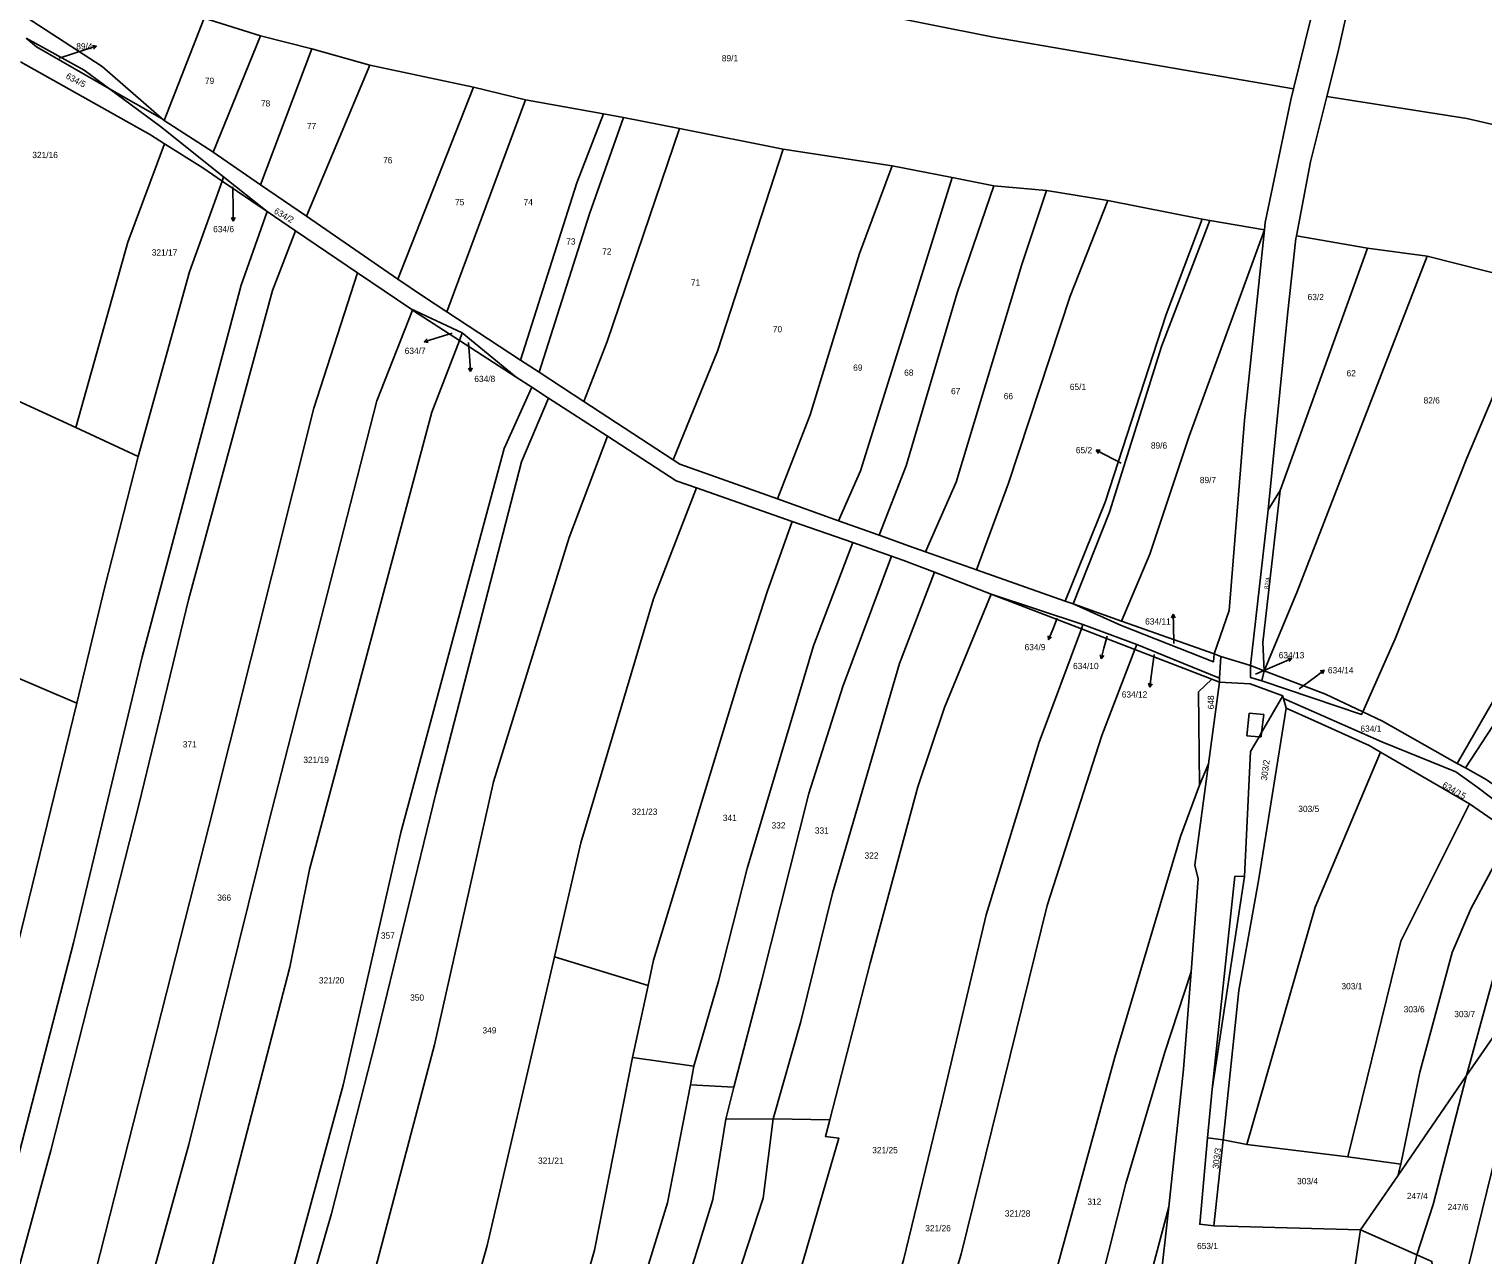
# Model space of a CAD drawing. Extents: x -744566 to -741843, y -1128407 to -1126744.
# Drawn here: x -743655.8 to -743260.5, y -1127679.3 to -1127345.9 of the extents above; entities that cross this region are included whole.
import ezdxf

# ---------------------------------------------------------------- set-up
doc = ezdxf.new("R2010")
doc.units = 0
for name, color, linetype in [('Hranice parcel', 7, 'Continuous'), ('Parcelní čísla', 7, 'Continuous'), ('Pop  PČ popisy', 7, 'Continuous'), ('Vnitřní kresba', 7, 'Continuous')]:
    doc.layers.add(name, color=color, linetype=linetype)

msp = doc.modelspace()

# ---------------------------------------------------------------- linework, layer by layer
at = {"layer": 'Hranice parcel'}
for p, q in [((-743312.01, -1127362.15), (-743304.91, -1127333.26)), ((-743608.18, -1127342.94), (-743619.02, -1127370.74)), ((-743608.18, -1127342.94), (-743592.88, -1127347.72)), ((-743592.88, -1127347.72), (-743605.72, -1127379.4)), ((-743592.88, -1127347.72), (-743578.94, -1127351.24)), ((-743578.94, -1127351.24), (-743592.83, -1127388.25)), ((-743578.94, -1127351.24), (-743563.19, -1127355.67)), ((-743563.19, -1127355.67), (-743580.36, -1127396.81)), ((-743563.19, -1127355.67), (-743534.99, -1127361.65)), ((-743534.99, -1127361.65), (-743555.5, -1127413.88)), ((-743534.99, -1127361.65), (-743520.78, -1127365.13)), ((-743520.78, -1127365.13), (-743542.21, -1127422.8)), ((-743520.78, -1127365.13), (-743499.65, -1127368.91)), ((-743499.65, -1127368.91), (-743494.17, -1127369.95)), ((-743494.17, -1127369.95), (-743478.91, -1127372.96)), ((-743478.91, -1127372.96), (-743450.74, -1127378.54)), ((-743592.83, -1127388.25), (-743605.72, -1127379.4)), ((-743450.74, -1127378.54), (-743421.13, -1127383.11)), ((-743603.32, -1127387.24), (-743602.9, -1127386.07)), ((-743602.9, -1127386.07), (-743591.07, -1127395.53)), ((-743421.13, -1127383.11), (-743404.84, -1127386.3)), ((-743591.07, -1127395.53), (-743603.32, -1127387.24)), ((-743580.36, -1127396.81), (-743592.83, -1127388.25)), ((-743404.84, -1127386.3), (-743393.46, -1127388.49)), ((-743393.46, -1127388.49), (-743379.14, -1127389.77)), ((-743379.14, -1127389.77), (-743362.5, -1127392.49)), ((-743362.5, -1127392.49), (-743336.87, -1127397.58)), ((-743591.07, -1127395.53), (-743583.33, -1127400.78)), ((-743555.5, -1127413.88), (-743580.36, -1127396.81)), ((-743336.87, -1127397.58), (-743334.8, -1127397.99)), ((-743583.33, -1127400.78), (-743566.53, -1127412.16)), ((-743334.8, -1127397.99), (-743319.91, -1127400.47)), ((-743291.86, -1127405.49), (-743315.66, -1127471.33)), ((-743291.86, -1127405.49), (-743311.22, -1127402.11)), ((-743275.71, -1127407.69), (-743291.86, -1127405.49)), ((-743244.94, -1127415.47), (-743275.71, -1127407.69)), ((-743566.53, -1127412.16), (-743552.04, -1127421.98)), ((-743551.54, -1127422.32), (-743552.04, -1127421.98)), ((-743552.04, -1127421.98), (-743538.08, -1127428.5)), ((-743538.8, -1127430.57), (-743551.54, -1127422.32)), ((-743522.16, -1127435.9), (-743542.21, -1127422.8)), ((-743538.8, -1127430.57), (-743538.08, -1127428.5)), ((-743538.08, -1127428.5), (-743523.36, -1127440.58)), ((-743695.91, -1127430.01), (-743643.11, -1127454.25)), ((-743523.36, -1127440.58), (-743538.8, -1127430.57)), ((-743517.11, -1127439.2), (-743522.16, -1127435.9)), ((-743523.36, -1127440.58), (-743519.14, -1127443.31)), ((-743504.93, -1127447.16), (-743517.11, -1127439.2)), ((-743519.14, -1127443.31), (-743514.57, -1127446.27)), ((-743514.57, -1127446.27), (-743498.56, -1127456.64)), ((-743480.64, -1127463.02), (-743504.93, -1127447.16)), ((-743643.11, -1127454.25), (-743626.1, -1127462.14)), ((-743474.35, -1127470.68), (-743448.36, -1127479.77)), ((-743318.91, -1127476.67), (-743315.66, -1127471.33)), ((-743435.76, -1127479.58), (-743452.29, -1127473.67)), ((-743318.91, -1127476.67), (-743323.69, -1127519.01)), ((-743448.36, -1127479.77), (-743431.85, -1127485.54)), ((-743424.7, -1127483.53), (-743435.76, -1127479.58)), ((-743431.85, -1127485.54), (-743421.29, -1127489.23)), ((-743398.17, -1127492.95), (-743412.06, -1127488.04)), ((-743409.64, -1127493.62), (-743394.17, -1127499.58)), ((-743374.07, -1127501.47), (-743398.17, -1127492.95)), ((-743369.67, -1127509.02), (-743394.17, -1127499.58)), ((-743394.17, -1127499.58), (-743369.28, -1127507.84)), ((-743371.91, -1127502.23), (-743374.07, -1127501.47)), ((-743371.91, -1127502.23), (-743358.75, -1127506.88)), ((-743369.67, -1127509.02), (-743369.28, -1127507.84)), ((-743369.28, -1127507.84), (-743354.63, -1127513.28)), ((-743358.75, -1127506.88), (-743333.57, -1127515.78)), ((-743355.14, -1127514.62), (-743369.67, -1127509.02)), ((-743355.14, -1127514.62), (-743354.63, -1127513.28)), ((-743334.26, -1127522.66), (-743355.14, -1127514.62)), ((-743354.63, -1127513.28), (-743332.1, -1127522.4)), ((-743331.74, -1127516.48), (-743333.57, -1127515.78)), ((-743331.74, -1127516.48), (-743332.1, -1127522.4)), ((-743323.69, -1127519.01), (-743331.74, -1127516.48)), ((-743323.69, -1127519.01), (-743320, -1127520.42)), ((-743320.65, -1127523.16), (-743320, -1127520.42)), ((-743642.79, -1127529.21), (-743661.46, -1127521.24)), ((-743335.16, -1127545.74), (-743332.17, -1127523.47)), ((-743332.17, -1127523.47), (-743334.26, -1127522.66)), ((-743332.1, -1127522.4), (-743332.17, -1127523.47)), ((-743314.71, -1127527.98), (-743314.91, -1127527.24)), ((-743314.01, -1127530.6), (-743314.71, -1127527.98)), ((-743265.25, -1127546.83), (-743254.82, -1127530.84)), ((-743264.18, -1127556.62), (-743288.35, -1127542.49)), ((-743337.56, -1127551.48), (-743335.16, -1127545.74)), ((-743265.25, -1127546.83), (-743267.48, -1127545.58)), ((-743252.73, -1127564.48), (-743264.18, -1127556.62)), ((-743230.52, -1127580.51), (-743264.95, -1127630.5)), ((-743487.51, -1127605.98), (-743512.98, -1127598.18)), ((-743491.75, -1127625.57), (-743487.51, -1127605.98)), ((-743475.06, -1127627.97), (-743491.75, -1127625.57)), ((-743475.06, -1127627.97), (-743475.93, -1127632.96)), ((-743264.95, -1127630.5), (-743283.69, -1127657.72)), ((-743475.93, -1127632.96), (-743464.14, -1127633.66)), ((-743464.14, -1127633.66), (-743466.39, -1127642.3)), ((-743453.46, -1127642.28), (-743466.39, -1127642.3)), ((-743453.46, -1127642.28), (-743438.1, -1127642.54)), ((-743335.37, -1127647.41), (-743331.17, -1127647.95)), ((-743333.67, -1127671.36), (-743331.17, -1127647.95)), ((-743324.73, -1127649.24), (-743331.17, -1127647.95)), ((-743324.73, -1127649.24), (-743297.22, -1127652.59)), ((-743282.86, -1127654.54), (-743297.22, -1127652.59)), ((-743283.69, -1127657.72), (-743282.86, -1127654.54)), ((-743283.69, -1127657.72), (-743293.8, -1127672.4)), ((-743333.67, -1127671.36), (-743293.8, -1127672.4)), ((-743301.55, -1127724.14), (-743293.8, -1127672.4)), ((-743293.8, -1127672.4), (-743278.45, -1127679.23)), ((-743287.1, -1127719.44), (-743278.45, -1127679.23))]:
    msp.add_line(p, q, dxfattribs=at)
for points in [[(-743312.01, -1127362.15), (-743393.56, -1127348.06), (-743446.91, -1127337.38), (-743506.37, -1127328.2), (-743565.99, -1127315.69), (-743593.43, -1127306.05), (-743622.26, -1127292.92), (-743649.24, -1127274.28)], [(-743677.33, -1127316.28), (-743670.54, -1127324.52), (-743664.92, -1127332.9), (-743656.54, -1127342.61), (-743635.91, -1127356.08), (-743619.02, -1127370.74)], [(-743296.23, -1127335.74), (-743299.98, -1127352.31), (-743302.98, -1127364.26)], [(-743656.57, -1127348.37), (-743640.77, -1127357.07), (-743633.94, -1127362.12)], [(-743656.57, -1127348.37), (-743653.73, -1127350.76), (-743633.94, -1127362.12)], [(-743618.94, -1127377.12), (-743622.79, -1127374.68), (-743658.11, -1127354.78)], [(-743633.94, -1127362.12), (-743620.04, -1127372.41), (-743602.9, -1127386.07)], [(-743619.02, -1127370.74), (-743619.65, -1127370.33), (-743633.94, -1127362.12)], [(-743319.91, -1127400.47), (-743319.7, -1127398.48), (-743312.73, -1127365.1), (-743312.01, -1127362.15)], [(-743302.98, -1127364.26), (-743307.41, -1127381.95), (-743311.22, -1127402.11)], [(-743199.65, -1127385.13), (-743264.92, -1127370.24), (-743302.98, -1127364.26)], [(-743499.65, -1127368.91), (-743506.82, -1127387.68), (-743522.16, -1127435.9)], [(-743494.17, -1127369.95), (-743503.41, -1127396.1), (-743517.11, -1127439.2)], [(-743605.72, -1127379.4), (-743605.84, -1127379.32), (-743619.02, -1127370.74)], [(-743478.91, -1127372.96), (-743498.61, -1127430.83), (-743504.93, -1127447.16)], [(-743643.11, -1127454.25), (-743628.97, -1127403.83), (-743618.94, -1127377.12)], [(-743603.32, -1127387.24), (-743608.59, -1127383.67), (-743618.94, -1127377.12)], [(-743450.74, -1127378.54), (-743468.63, -1127433.52), (-743480.64, -1127463.02)], [(-743421.13, -1127383.11), (-743430.01, -1127406.91), (-743443.41, -1127450.8), (-743452.29, -1127473.67)], [(-743603.32, -1127387.24), (-743612.17, -1127411.89), (-743626.1, -1127462.14)], [(-743404.84, -1127386.3), (-743416.15, -1127422.6), (-743429.78, -1127466.03), (-743435.76, -1127479.58)], [(-743393.46, -1127388.49), (-743403.43, -1127417.65), (-743417.28, -1127464.67), (-743424.7, -1127483.53)], [(-743379.14, -1127389.77), (-743385.89, -1127409.89), (-743403.69, -1127469.09), (-743412.06, -1127488.04)], [(-743362.5, -1127392.49), (-743372.73, -1127418.53), (-743389.53, -1127469.42), (-743398.17, -1127492.95)], [(-743681.73, -1127737.55), (-743673.31, -1127708.75), (-743643.68, -1127594.43), (-743625.08, -1127516.64), (-743598.16, -1127415.52), (-743591.07, -1127395.53)], [(-743374.07, -1127501.47), (-743363.18, -1127474.59), (-743346.61, -1127423.47), (-743336.87, -1127397.58)], [(-743583.33, -1127400.78), (-743589.64, -1127417.03), (-743612.49, -1127501.11), (-743625.94, -1127556.86), (-743649.9, -1127650.85), (-743673.66, -1127737.68)], [(-743371.91, -1127502.23), (-743362, -1127477.23), (-743347.91, -1127432.2), (-743334.8, -1127397.99)], [(-743358.75, -1127506.88), (-743351.05, -1127488.73), (-743340.35, -1127456.63), (-743319.91, -1127400.47)], [(-743333.57, -1127515.78), (-743329.5, -1127504.03), (-743325.36, -1127452.28), (-743319.91, -1127400.47)], [(-743311.22, -1127402.11), (-743311.36, -1127402.88), (-743313.62, -1127423.64), (-743318.91, -1127476.67)], [(-743320, -1127520.42), (-743311.15, -1127499.13), (-743275.71, -1127407.69)], [(-743566.53, -1127412.16), (-743578.37, -1127448.95), (-743606.94, -1127562.76), (-743640.25, -1127693.79), (-743653.09, -1127738.43)], [(-743542.21, -1127422.8), (-743548.56, -1127418.65), (-743555.5, -1127413.88)], [(-743244.94, -1127415.47), (-743264.86, -1127462.59), (-743284.35, -1127511.68), (-743293.15, -1127531.6)], [(-743551.54, -1127422.32), (-743561.28, -1127447), (-743590.72, -1127561.84), (-743612.33, -1127649.25), (-743636.86, -1127737.44)], [(-743267.48, -1127545.58), (-743248.98, -1127513.51), (-743227.96, -1127466.68), (-743207.37, -1127426.59)], [(-743621.23, -1127735.75), (-743612.44, -1127707.12), (-743584.91, -1127601.01), (-743579.58, -1127574.43), (-743546.31, -1127450.09), (-743538.8, -1127430.57)], [(-743599.16, -1127738.75), (-743570.37, -1127633.12), (-743554.73, -1127564.38), (-743526.58, -1127459.91), (-743519.14, -1127443.31)], [(-743514.57, -1127446.27), (-743521.89, -1127463.56), (-743545.21, -1127553.77), (-743561.74, -1127621.6), (-743573.61, -1127667.99), (-743594.04, -1127739.28)], [(-743498.56, -1127456.64), (-743508.94, -1127484.15), (-743529.52, -1127550.64), (-743545.56, -1127622.11), (-743562.33, -1127685.66), (-743579.85, -1127741.23)], [(-743498.56, -1127456.64), (-743479.85, -1127468.76), (-743474.35, -1127470.68)], [(-743626.1, -1127462.14), (-743635.23, -1127497.57), (-743642.79, -1127529.21)], [(-743452.29, -1127473.67), (-743478.87, -1127464.17), (-743480.64, -1127463.02)], [(-743474.35, -1127470.68), (-743486.04, -1127500.8), (-743505.77, -1127567.21), (-743512.98, -1127598.18)], [(-743315.66, -1127471.33), (-743320.31, -1127512.72), (-743320, -1127520.42)], [(-743487.51, -1127605.98), (-743486.02, -1127599.12), (-743462.28, -1127521.15), (-743455.14, -1127498.91), (-743448.36, -1127479.77)], [(-743412.06, -1127488.04), (-743416.38, -1127486.51), (-743424.7, -1127483.53)], [(-743431.85, -1127485.54), (-743442.53, -1127513.63), (-743460.53, -1127574.17), (-743468.34, -1127604.77), (-743475.06, -1127627.97)], [(-743421.29, -1127489.23), (-743434.5, -1127524.7), (-743443.83, -1127553.78), (-743456.63, -1127604.77), (-743464.14, -1127633.66)], [(-743421.29, -1127489.23), (-743418.24, -1127490.3), (-743409.64, -1127493.62)], [(-743409.64, -1127493.62), (-743419.11, -1127518.4), (-743437.32, -1127580.9), (-743446, -1127615.82), (-743453.46, -1127642.28)], [(-743394.17, -1127499.58), (-743406.86, -1127530.38), (-743414.11, -1127551.95), (-743427.12, -1127599.89), (-743438.1, -1127642.54)], [(-743333.57, -1127515.78), (-743333.72, -1127517.94), (-743359.08, -1127507.99), (-743371.91, -1127502.23)], [(-743448.1, -1127780.84), (-743443.18, -1127766.73), (-743418.02, -1127680.71), (-743407.6, -1127637.74), (-743395.56, -1127586.74), (-743381.16, -1127539.8), (-743369.67, -1127509.02)], [(-743434.17, -1127788.45), (-743427.78, -1127767.16), (-743415.63, -1127722.89), (-743402.41, -1127679.01), (-743378.99, -1127584.19), (-743364.14, -1127538.04), (-743355.14, -1127514.62)], [(-743320.65, -1127523.16), (-743323.7, -1127522.24), (-743323.69, -1127519.01)], [(-743320, -1127520.42), (-743303.35, -1127526.75), (-743293.15, -1127531.6)], [(-743334.26, -1127522.66), (-743337.82, -1127526.16), (-743337.56, -1127551.48)], [(-743332.17, -1127523.47), (-743323.8, -1127523.97), (-743314.91, -1127527.24)], [(-743293.15, -1127531.6), (-743293.49, -1127532.29), (-743320.65, -1127523.16)], [(-743314.91, -1127527.24), (-743320.68, -1127537.21), (-743321.34, -1127538.34), (-743323.67, -1127542.37), (-743325.37, -1127576.31), (-743334.16, -1127634.18), (-743335.37, -1127647.41)], [(-743314.71, -1127527.98), (-743288.02, -1127539.72), (-743267.92, -1127547.88), (-743262.15, -1127552), (-743250.66, -1127560.62)], [(-743642.79, -1127529.21), (-743664.09, -1127615.99), (-743695.53, -1127736.94)], [(-743331.17, -1127647.95), (-743326.84, -1127607.36), (-743321.41, -1127576.97), (-743314.01, -1127530.6)], [(-743288.35, -1127542.49), (-743291.43, -1127540.69), (-743306.33, -1127533.99), (-743314.01, -1127530.6)], [(-743267.48, -1127545.58), (-743287.81, -1127534.14), (-743293.15, -1127531.6)], [(-743288.35, -1127542.49), (-743306.14, -1127584.68), (-743324.73, -1127649.24)], [(-743339.88, -1127602.23), (-743337.94, -1127576.95), (-743338.86, -1127573.29), (-743335.16, -1127545.74)], [(-743191.76, -1127600.69), (-743213.04, -1127583.89), (-743235.8, -1127566.59), (-743259.6, -1127550), (-743265.25, -1127546.83)], [(-743337.56, -1127551.48), (-743342.72, -1127565.43), (-743360.58, -1127625.49), (-743392.64, -1127742.44), (-743405.3, -1127787.74)], [(-743297.22, -1127652.59), (-743282.79, -1127593.92), (-743264.18, -1127556.62)], [(-743282.86, -1127654.54), (-743277.65, -1127629.53), (-743268.85, -1127597.04), (-743263.84, -1127585.18), (-743252.73, -1127564.48)], [(-743264.95, -1127630.5), (-743257.74, -1127603.98), (-743251.48, -1127589.3), (-743241.42, -1127572.24)], [(-743270.64, -1127711.51), (-743265.43, -1127686.37), (-743248.78, -1127618.41), (-743240.66, -1127598.71), (-743230.04, -1127580.88)], [(-743512.98, -1127598.18), (-743531.28, -1127676.73), (-743550.89, -1127746.78)], [(-743339.88, -1127602.23), (-743346.97, -1127624.14), (-743357.58, -1127659.83), (-743366.95, -1127696.84), (-743386.06, -1127772.64), (-743386.45, -1127778.59)], [(-743374.07, -1127772.46), (-743345.92, -1127666.2), (-743341.91, -1127628.76), (-743339.88, -1127602.23)], [(-743520.82, -1127743.45), (-743502.02, -1127678), (-743491.75, -1127625.57)], [(-743278.45, -1127679.23), (-743274.02, -1127665.56), (-743264.95, -1127630.5)], [(-743475.93, -1127632.96), (-743482.22, -1127665.09), (-743506.51, -1127743.94), (-743520.33, -1127808.71)], [(-743466.39, -1127642.3), (-743469.86, -1127664.22), (-743494.95, -1127745.55), (-743511, -1127814.57)], [(-743453.46, -1127642.28), (-743456.19, -1127663.78), (-743479.83, -1127736.34), (-743486.56, -1127767.82), (-743500.98, -1127829.09)], [(-743438.1, -1127642.54), (-743439.27, -1127647.07), (-743435.59, -1127647.51), (-743460.31, -1127732.22), (-743470.88, -1127766.12)], [(-743335.37, -1127647.41), (-743337.51, -1127670.9), (-743333.67, -1127671.36)], [(-743278.45, -1127679.23), (-743274.37, -1127681.04), (-743273.1, -1127691.93), (-743283.11, -1127716.84)]]:
    msp.add_lwpolyline(points, dxfattribs=at)
at = {"layer": 'Pop  PČ popisy'}
for p, q in [((-743637.486, -1127350.553), (-743638.593, -1127350.386)), ((-743647.59, -1127353.8), (-743640.34, -1127351.48)), ((-743640.34, -1127351.48), (-743637.486, -1127350.553)), ((-743637.486, -1127350.553), (-743638.284, -1127351.338)), ((-743600.38, -1127388.76), (-743600.32, -1127395.1)), ((-743600.268, -1127398.101), (-743600.786, -1127397.108)), ((-743600.32, -1127395.1), (-743600.268, -1127398.101)), ((-743600.268, -1127398.101), (-743599.784, -1127397.09)), ((-743540.79, -1127428.58), (-743545.51, -1127430.04)), ((-743545.51, -1127430.04), (-743548.38, -1127430.917)), ((-743548.38, -1127430.917), (-743547.569, -1127430.146)), ((-743548.38, -1127430.917), (-743547.276, -1127431.103)), ((-743536.35, -1127431.11), (-743535.97, -1127436.06)), ((-743535.97, -1127436.06), (-743535.761, -1127439.054)), ((-743535.761, -1127439.054), (-743536.33, -1127438.09)), ((-743535.761, -1127439.054), (-743535.331, -1127438.02)), ((-743363.05, -1127461.8), (-743365.7, -1127460.391)), ((-743365.7, -1127460.391), (-743364.58, -1127460.419)), ((-743365.7, -1127460.391), (-743365.051, -1127461.303)), ((-743358.9, -1127463.98), (-743363.05, -1127461.8)), ((-743376.23, -1127506.05), (-743377.48, -1127509.19)), ((-743344.732, -1127504.999), (-743345.216, -1127506.01)), ((-743344.68, -1127508), (-743344.732, -1127504.999)), ((-743344.732, -1127504.999), (-743344.214, -1127505.992)), ((-743344.57, -1127512.94), (-743344.68, -1127508)), ((-743378.604, -1127511.972), (-743378.693, -1127510.856)), ((-743377.48, -1127509.19), (-743378.604, -1127511.972)), ((-743378.604, -1127511.972), (-743377.765, -1127511.232)), ((-743362.69, -1127511.01), (-743363.56, -1127514.22)), ((-743364.337, -1127517.119), (-743364.561, -1127516.022)), ((-743363.56, -1127514.22), (-743364.337, -1127517.119)), ((-743364.337, -1127517.119), (-743363.594, -1127516.281)), ((-743349.88, -1127515.95), (-743350.69, -1127521.88)), ((-743322.32, -1127521.3), (-743315.22, -1127518.22)), ((-743315.22, -1127518.22), (-743312.458, -1127517.047)), ((-743312.458, -1127517.047), (-743313.575, -1127516.978)), ((-743312.458, -1127517.047), (-743313.184, -1127517.9)), ((-743306.07, -1127522.05), (-743303.673, -1127520.244)), ((-743303.673, -1127520.244), (-743304.774, -1127520.447)), ((-743303.673, -1127520.244), (-743304.172, -1127521.247)), ((-743351.108, -1127524.852), (-743351.464, -1127523.79)), ((-743350.69, -1127521.88), (-743351.108, -1127524.852)), ((-743351.108, -1127524.852), (-743350.472, -1127523.93)), ((-743310.46, -1127525.32), (-743306.07, -1127522.05))]:
    msp.add_line(p, q, dxfattribs=at)
at = {"layer": 'Vnitřní kresba'}
for p, q in [((-743324.66, -1127538.05), (-743324.03, -1127531.89)), ((-743324.03, -1127531.89), (-743320.11, -1127532.27)), ((-743320.68, -1127537.21), (-743320.11, -1127532.27)), ((-743324.66, -1127538.05), (-743321.34, -1127538.34)), ((-743321.34, -1127538.34), (-743320.82, -1127538.39)), ((-743320.82, -1127538.39), (-743320.68, -1127537.21)), ((-743334.16, -1127634.18), (-743327.93, -1127576.22)), ((-743327.93, -1127576.22), (-743325.37, -1127576.31)), ((-743356.23, -1127757.98), (-743345.92, -1127666.2))]:
    msp.add_line(p, q, dxfattribs=at)

# ---------------------------------------------------------------- texts
at = {"layer": 'Parcelní čísla'}
for s, p in [('89/4', (-743642.962, -1127351.42)), ('89/1', (-743467.44, -1127354.66)), ('79', (-743607.98, -1127360.8)), ('78', (-743592.75, -1127366.94)), ('77', (-743580.24, -1127373.09)), ('321/16', (-743654.91, -1127380.98)), ('76', (-743559.54, -1127382.42)), ('75', (-743539.99, -1127393.8)), ('74', (-743521.34, -1127393.8)), ('634/6', (-743605.756, -1127401.13)), ('321/17', (-743622.44, -1127407.48)), ('73', (-743509.74, -1127404.49)), ('72', (-743499.96, -1127407.22)), ('71', (-743475.85, -1127415.64)), ('63/2', (-743308.18, -1127419.61)), ('70', (-743453.57, -1127428.34)), ('634/7', (-743553.666, -1127434.23)), ('69', (-743431.74, -1127438.81)), ('634/8', (-743534.74, -1127441.883)), ('68', (-743417.86, -1127440.18)), ('62', (-743297.59, -1127440.34)), ('67', (-743405.13, -1127445.19)), ('66', (-743390.8, -1127446.55)), ('65/1', (-743372.83, -1127444.05)), ('82/6', (-743276.65, -1127447.71)), ('65/2', (-743371.182, -1127461.25)), ('89/6', (-743350.79, -1127459.98)), ('89/7', (-743337.48, -1127469.37)), ('634/11', (-743352.351, -1127507.833)), ('634/9', (-743385.126, -1127514.813)), ('634/13', (-743316.031, -1127517.01)), ('634/10', (-743371.951, -1127519.953)), ('634/14', (-743302.66, -1127521.11)), ('634/12', (-743358.711, -1127527.683)), ('634/1', (-743293.81, -1127536.99)), ('371', (-743614, -1127541.25)), ('321/19', (-743581.22, -1127545.47)), ('321/23', (-743491.92, -1127559.57)), ('341', (-743467.17, -1127561.25)), ('303/5', (-743310.71, -1127558.81)), ('332', (-743453.93, -1127563.29)), ('331', (-743442.14, -1127564.69)), ('322', (-743428.65, -1127571.49)), ('366', (-743604.63, -1127582.95)), ('357', (-743560.15, -1127593.26)), ('321/20', (-743577.01, -1127605.44)), ('303/1', (-743298.98, -1127607.03)), ('350', (-743552.19, -1127610.13)), ('303/6', (-743282.05, -1127613.3)), ('303/7', (-743268.3, -1127614.6)), ('349', (-743532.52, -1127619.03)), ('321/25', (-743426.55, -1127651.61)), ('321/21', (-743517.42, -1127654.48)), ('303/4', (-743311.04, -1127660.04)), ('247/4', (-743281.19, -1127664.08)), ('312', (-743368.06, -1127665.63)), ('247/6', (-743270.11, -1127667.08)), ('321/28', (-743390.5, -1127668.83)), ('321/26', (-743412.13, -1127672.84)), ('653/1', (-743338.243, -1127677.68))]:
    msp.add_text(s, height=1.7, dxfattribs=at).set_placement(p)
for s, height, rotation, p in [('634/5', 1.7, 332, (-743645.959, -1127359.19)), ('634/2', 1.7, 330, (-743589.385, -1127395.866)), ('82/4', 1.19, 83, (-743318.789, -1127498.242)), ('648', 1.7, 91, (-743333.59, -1127530.875)), ('303/2', 1.7, 82, (-743319.258, -1127550.348)), ('634/15', 1.7, 330, (-743271.745, -1127551.946)), ('303/3', 1.7, 83, (-743332.386, -1127655.923))]:
    msp.add_text(s, height=height, rotation=rotation, dxfattribs=at).set_placement(p)

doc.saveas('drawing.dxf')
